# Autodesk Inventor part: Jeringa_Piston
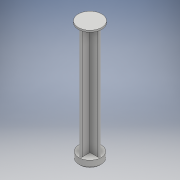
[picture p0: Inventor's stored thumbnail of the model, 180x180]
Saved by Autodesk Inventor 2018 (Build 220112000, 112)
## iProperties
Part Number: Jeringa_Piston
Material: Genérico
Document SubType Name: Modeling
Designer: ULISES
Density: 1 g/cm^3
Appearance: Valor por defecto
Author: ULISES
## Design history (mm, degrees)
sketch "Boceto1"
  geometry: C1 r 2 at (0, 0); 1 further point
  constraints: 1 centre point, 1 coincident
  dimensions: "d0" = 4 diameter of C1
extrude "Extrusión1" new body sketch "Boceto1" distance "d1" = 2; taper "d2" = 0 deg
sketch "Boceto2"
  geometry: C1 r 3.5 at (0, 0); 1 further point
  constraints: 1 centre point, 1 coincident
  dimensions: "d3" = 7 diameter of C1
extrude "Extrusión2" join sketch "Boceto2" distance "d4" = 7; taper "d5" = 0 deg
sketch "Boceto3"
  geometry: C1 r 13.5 at (0, 0); 1 further point
  constraints: 1 centre point, 1 coincident
  dimensions: "d6" = 27 diameter of C1
extrude "Extrusión3" join sketch "Boceto3" distance "d7" = 115; taper "d8" = 0 deg
sketch "Boceto4"
  geometry: L1 (0, 10)-(0, -10); L2 (13.5, 10)-(13.5, -10); L3 (-13.5, -10)-(-13.5, 10); C1 r 13.5 at (0, 0) reference; A1 r 13.5 centre (0, 10) between (13.5, 10) and (-13.5, 10); A2 r 13.5 centre (0, -10) between (-13.5, -10) and (13.5, -10); 2 further points
  constraints: 8 end point, 6 tangent, 4 point on circle, 2 centre point, 1 coincident, 1 midpoint, 1 parallel, 1 vertical
  dimensions: "d9" = 20 distance of L1.start L1.end
extrude "Extrusión4" join sketch "Boceto4" distance "d10" = 1.5; taper "d11" = 0 deg
sketch "Boceto5"
  geometry: L1 (0, -7.75)-(0, 7.75); L2 (1, -7.75)-(1, 7.75); L3 (-1, 7.75)-(-1, -7.75); L4 (7.75, 0)-(-7.75, 0); L5 (7.75, 1)-(-7.75, 1); L6 (-7.75, -1)-(7.75, -1); A1 r 1 centre (0, -7.75) between (-1, -7.75) and (1, -7.75); A2 r 1 centre (0, 7.75) between (1, 7.75) and (-1, 7.75); A3 r 1 centre (7.75, 0) between (7.75, -1) and (7.75, 1); A4 r 1 centre (-7.75, 0) between (-7.75, 1) and (-7.75, -1); 3 further points
  constraints: 16 end point, 8 point on circle, 8 tangent, 4 centre point, 2 coincident, 2 midpoint, 2 parallel, 1 horizontal, 1 vertical
  dimensions: "d12" = 15.5 distance of L1.start L1.end; "d13" = 15.5 distance of L4.start L4.end; "d14" = 2 distance between parallel lines of L3 L2; "d15" = 2 distance between parallel lines of L6 L5
extrude "Extrusión5" join sketch "Boceto5" distance "d16" = 96.5; taper "d17" = 0 deg
sketch "Boceto6"
  geometry: C1 r 10 at (0, 0); 1 further point
  constraints: 1 centre point, 1 coincident
  dimensions: "d18" = 20 diameter of C1
extrude "Extrusión6" join sketch "Boceto6" distance "d19" = 1.5; taper "d20" = 0 deg
sketch "Boceto7"
  geometry: C1 r 26.926 at (0, 0); 1 further point
  constraints: 1 centre point, 1 coincident
extrude "Extrusión7" cut sketch "Boceto7" distance "d21" = 124; taper "d22" = 0 deg
sketch "Boceto8"
  geometry: C1 r 9.5 at (0, 0); 1 further point
  constraints: 1 centre point, 1 coincident
  dimensions: "d23" = 19 diameter of C1
extrude "Extrusión8" join sketch "Boceto8" distance "d24" = 6; taper "d25" = 0 deg
chamfer "Chaflán1" distance "d26" = 1; stored, may be unused: second distance "d27" = 2, angle "d28" = 45 deg
node "Sólido1"
